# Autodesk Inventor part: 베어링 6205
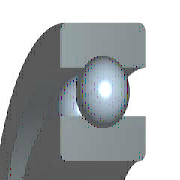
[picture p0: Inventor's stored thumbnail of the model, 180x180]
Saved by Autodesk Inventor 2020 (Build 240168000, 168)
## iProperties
Created: 2009-02
Part Number: 베어링 6205
Material: 강, 연강
Description: 깊은 그루브 볼 베어링
Document SubType Name: Modeling
Standard: KS B 2023
Designer: 진현석
Standards Organization: KS
Language: ko-KR
Size Designation: 6205 - 25 x 52 x 15
Categories: <MemberInstance><Categories><Category DisplayName="샤프트 부품" InternalName="7f7aeb1f-a693-4053-b835-cee3144e0d98" Mnemonic="SHFT"><Category DisplayName="베어링" Inter
Density: 1 g/cm^3
Appearance: 강철(1)
IsCustomPart: 1
Author: 진현석
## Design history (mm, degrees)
sketch "스케치" dims "d0" = 7.02 (= -0.26 x WD + 0.26 x BD)
  geometry: L1 (3.99, 19.25)-(11.01, 19.25); L2 (7.5, 19.25)-(7.5, 15.74); L3 (7.5, 19.25)-(7.5, 22.76); L4 (4.892, 16.901)-(0, 16.901); L5 (0, 12.5)-(15, 12.5); L6 (4.892, 21.599)-(0, 21.599); L7 (0, 26)-(15, 26); L8 (15, 12.5)-(15, 16.901); L9 (10.108, 16.901)-(15, 16.901); L10 (10.108, 21.599)-(15, 21.599); L11 (15, 26)-(15, 21.599); L12 (-1.4, 0)-(8.4, 0) reference; L13 (0, -0.3)-(0, 5.3) reference
  constraints: 22 end point, 4 point on line, 2 collinear, 2 perpendicular, 2 symmetric about line, 1 midpoint, 1 parallel, 14 other
  dimensions: "d9" = 25 diameter of L5 L12 (= WD); "d11" = 52 diameter of L7 L12 (= BD); "d12" = 15 distance between parallel lines of L8 L13 (= KB); "d13" = 33.802 diameter of L9 L12 (= 0.326 x BD + 0.674 x WD)
revolve "본체" stored, may be unused: angle "d6" = 90 deg
revolve "볼" stored, may be unused: angle "d7" = 90 deg
pattern_circular "IDS_ARRAYBALL[SIMPL:T]" dims angle "d3" = 360 deg
body "Solid1"
fillet "모깎기1" dims "d1" = 1 (= KRS)
other parameters: "WD" = 25 [user parameter; used in 5 equation terms], "BD" = 52 [user parameter; used in 5 equation terms], "KB" = 15 [user parameter; used in 1 equation term], "KRS" = 1 [user parameter; used in 1 equation term], "d4" = 0, "d5" = 0, "d8" = 0, "d14" = 0, "d15" = 0, "BBA" = 0 [user parameter], "BC0" = 7800000 [user parameter], "BC" = 1.4e+07 [user parameter], "BR" = 26 (= 0.5 x BD) [user parameter], "WR" = 12.5 (= 0.5 x WD) [user parameter]
